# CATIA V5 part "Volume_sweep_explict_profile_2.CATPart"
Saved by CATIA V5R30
Part number: Part1
Bounding box of the stored display mesh (mm): x -0.366 to 107.273, y -258.378 to 1.302, z -19.914 to 111.945
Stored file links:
  D:\PROJECTS\CATIA V56R 2020\Resources\Parts File\c17_catia_v6_6r2020_prt\Volume_sweep_explict_profile_2.CATPart
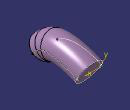
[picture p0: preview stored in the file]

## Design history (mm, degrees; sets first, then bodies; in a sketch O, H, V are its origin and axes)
Set1
  Sketch1 on yz-plane, origin (0, 0, 0), H (0, 1, 0), V (0, 0, 1)
    spline S1 through (-23.0016, 27.4581) (-75.0426, 47.0094) (-171.9366, 48.7346) (-214.202, 27.4581)
  Plane1: type Offset, RefPlane yz-plane, Offset 107
  Sketch2 on Plane1, origin (107, 0, 0), H (0, 1, 0), V (0, 0, 1)
    spline S1 through (-23.0016, 27.4581) (-104.0993, 55.4238) (-183.694, 56.9883) (-214.202, 27.4581)
    reference projected point E1 (-214.202, 27.4581) from vertex of Sketch1
    reference projected point E2 (-23.0016, 27.4581) from vertex of Sketch1
    point P1 (-214.202, 27.4581)
    point P2 (-23.0016, 27.4581)
    coincidence: P1 E1, P2 E2
  Plane2: type Normal, Curve Sketch1, RefPoint vertex of Sketch1, Ratio 0
  Sketch3 on Plane2, origin (0, -29.3756, 14.8457), H (1, 0, 0), V (0, 0.451, 0.8925)
    circle A1 centre (53.5, 14.5287) radius 53.5015
    reference projected point E1 (107, 14.1316) from Sketch2.P2
    reference projected point E2 (0, 14.1316) from vertex of Sketch1
    coincidence: A1 E1, A1 E2
  Sketch4 on Plane2, origin (0, -29.3756, 14.8457), H (1, 0, 0), V (0, 0.451, 0.8925)
    point P1 (107, 14.1316)
    reference projected point E1 (107, 14.1316) from Sketch2.P2
    coincidence: P1 E1
  Sketch5 on Plane2, origin (0, -29.3756, 14.8457), H (1, 0, 0), V (0, 0.451, 0.8925)
    point P1 (0, 14.1316)
    reference projected point E1 (0, 14.1316) from vertex of Sketch1
    coincidence: P1 E1
  Sweep1: type Unspec, Profile Sketch3, Guide (Sketch2; Sketch1), FittingPoints (Sketch4; Sketch5)
Body1 (main body)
